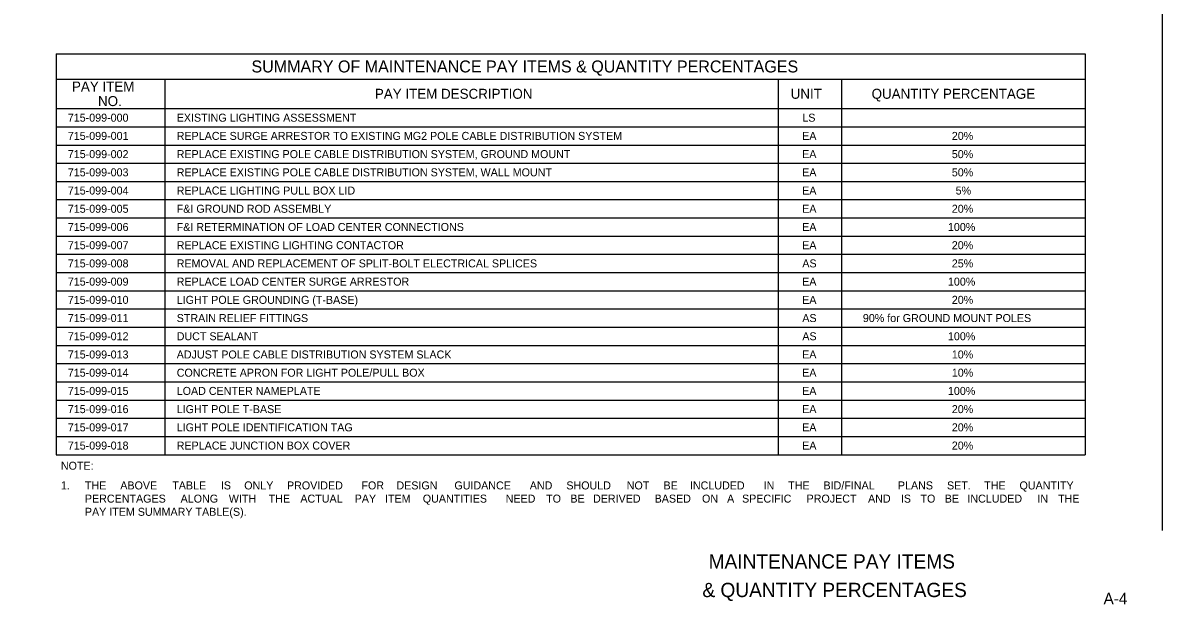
# Model space of a CAD drawing. Extents: x -55 to 2471539, y -90 to 3608906.
# Drawn here: x 543 to 1540, y -64 to 445 of the extents above; entities that cross this region are included whole.
import ezdxf

# ---------------------------------------------------------------- set-up
doc = ezdxf.new("R2010")
doc.units = 0
for name, color, linetype in [('NonPlottingEle_dp', 7, 'Continuous'), ('SumBoxBorder_dp', 7, 'Continuous'), ('SumBoxLines_dp', 7, 'Continuous'), ('SumBoxLinesMin_dp', 7, 'Continuous'), ('TextLabel', 7, 'Continuous'), ('TextMisc', 7, 'Continuous'), ('TextShtNo', 7, 'Continuous')]:
    doc.layers.add(name, color=color, linetype=linetype)

msp = doc.modelspace()

# ---------------------------------------------------------------- linework, layer by layer
at = {"layer": 'NonPlottingEle_dp'}
msp.add_lwpolyline([(0, 0), (0, 960), (1540, 960), (1540, 0)], dxfattribs=at)
at = {"layer": 'SumBoxBorder_dp'}
for p, q in [((572.5, 417.37), (1472.5, 417.37)), ((572.5, 417.37), (572.5, 66.47)), ((1472.5, 417.37), (1472.5, 66.47)), ((572.5, 369.52), (1472.5, 369.52)), ((572.5, 369.52), (1472.5, 369.52)), ((572.5, 66.47), (1472.5, 66.47))]:
    msp.add_line(p, q, dxfattribs=at)
at = {"layer": 'SumBoxLines_dp'}
for p, q in [((572.5, 395.42), (1472.5, 395.42)), ((572.5, 395.42), (1472.5, 395.42)), ((667.75, 395.42), (667.75, 66.47)), ((667.75, 395.42), (667.75, 66.47)), ((1204, 395.42), (1204, 66.47)), ((1204, 395.42), (1204, 66.47)), ((1259.5, 395.42), (1259.5, 66.47)), ((1259.5, 395.42), (1259.5, 66.47)), ((572.5, 353.57), (1472.5, 353.57)), ((580.75, 353.57), (1204, 353.57))]:
    msp.add_line(p, q, dxfattribs=at)
at = {"layer": 'SumBoxLinesMin_dp'}
for p, q in [((1204, 353.57), (1259.5, 353.57)), ((572.5, 337.62), (1259.5, 337.62)), ((572.5, 337.62), (1472.5, 337.62)), ((572.5, 321.67), (1472.5, 321.67)), ((572.5, 321.67), (1472.5, 321.67)), ((572.5, 305.72), (1472.5, 305.72)), ((572.5, 305.72), (1472.5, 305.72)), ((572.5, 289.77), (1472.5, 289.77)), ((572.5, 289.77), (1472.5, 289.77)), ((572.5, 273.82), (1472.5, 273.82)), ((572.5, 273.82), (1472.5, 273.82)), ((572.5, 257.87), (1472.5, 257.87)), ((572.5, 257.87), (1472.5, 257.87)), ((572.5, 241.92), (1472.5, 241.92)), ((572.5, 241.92), (1472.5, 241.92)), ((572.5, 225.97), (1472.5, 225.97)), ((572.5, 225.97), (1472.5, 225.97)), ((572.5, 210.02), (1472.5, 210.02)), ((572.5, 210.02), (1472.5, 210.02)), ((572.5, 194.07), (1472.5, 194.07)), ((572.5, 194.07), (1472.5, 194.07)), ((572.5, 178.12), (1472.5, 178.12)), ((572.5, 178.12), (1472.5, 178.12)), ((572.5, 162.17), (1472.5, 162.17)), ((572.5, 162.17), (1472.5, 162.17)), ((572.5, 146.22), (1472.5, 146.22)), ((572.5, 146.22), (1472.5, 146.22)), ((572.5, 130.27), (1472.5, 130.27)), ((572.5, 130.27), (1472.5, 130.27)), ((572.5, 114.32), (1472.5, 114.32)), ((580.75, 114.32), (667.75, 114.32)), ((676, 114.32), (1472.5, 114.32)), ((572.5, 98.37), (1472.5, 98.37)), ((580.75, 98.37), (667.75, 98.37)), ((1259.5, 98.37), (1472.5, 98.37)), ((572.5, 82.42), (1472.5, 82.42)), ((580.75, 82.42), (667.75, 82.42)), ((1259.5, 82.42), (1472.5, 82.42))]:
    msp.add_line(p, q, dxfattribs=at)

# ---------------------------------------------------------------- texts
at = {"layer": 'TextLabel'}
for s, height, p in [('SUMMARY OF MAINTENANCE PAY ITEMS & QUANTITY PERCENTAGES', 10.5, (743.38, 401.15)), ('PAY ITEM', 8.75, (586.39, 384.47)), ('NO.', 8.75, (609.17, 371.72)), ('PAY ITEM DESCRIPTION', 8.75, (851.34, 378.1)), ('UNIT', 8.75, (1215.03, 378.1)), ('QUANTITY PERCENTAGE', 8.75, (1285.82, 378.1)), ('715-099-000', 7, (582.75, 358.05)), ('EXISTING LIGHTING ASSESSMENT', 7, (678, 358.05)), ('LS', 7, (1225.22, 358.05)), ('715-099-001', 7, (582.75, 342.1)), ('REPLACE SURGE ARRESTOR TO EXISTING MG2 POLE CABLE DISTRIBUTION SYSTEM', 7, (678, 342.1)), ('EA', 7, (1225.07, 342.1)), ('20%', 7, (1355.97, 342.1)), ('715-099-002', 7, (582.75, 326.15)), ('REPLACE EXISTING POLE CABLE DISTRIBUTION SYSTEM, GROUND MOUNT', 7, (678, 326.15)), ('EA', 7, (1225.07, 326.15)), ('50%', 7, (1355.97, 326.15)), ('715-099-003', 7, (582.75, 310.2)), ('REPLACE EXISTING POLE CABLE DISTRIBUTION SYSTEM, WALL MOUNT', 7, (678, 310.2)), ('EA', 7, (1225.07, 310.2)), ('50%', 7, (1355.97, 310.2)), ('715-099-004', 7, (582.75, 294.25)), ('REPLACE LIGHTING PULL BOX LID', 7, (678, 294.25)), ('EA', 7, (1225.07, 294.25)), ('5%', 7, (1359.35, 294.25)), ('715-099-005', 7, (582.75, 278.3)), ('F&I GROUND ROD ASSEMBLY', 7, (678, 278.3)), ('EA', 7, (1225.07, 278.3)), ('20%', 7, (1355.97, 278.3)), ('715-099-006', 7, (582.75, 262.35)), ('F&I RETERMINATION OF LOAD CENTER CONNECTIONS', 7, (678, 262.35)), ('EA', 7, (1225.07, 262.35)), ('100%', 7, (1352.58, 262.35)), ('715-099-007', 7, (582.75, 246.4)), ('REPLACE EXISTING LIGHTING CONTACTOR', 7, (678, 246.4)), ('EA', 7, (1225.07, 246.4)), ('20%', 7, (1355.97, 246.4)), ('715-099-008', 7, (582.75, 230.45)), ('REMOVAL AND REPLACEMENT OF SPLIT-BOLT ELECTRICAL SPLICES', 7, (678, 230.45)), ('AS', 7, (1225.22, 230.45)), ('25%', 7, (1355.97, 230.45)), ('715-099-009', 7, (582.75, 214.5)), ('REPLACE LOAD CENTER SURGE ARRESTOR', 7, (678, 214.5)), ('EA', 7, (1225.07, 214.5)), ('100%', 7, (1352.58, 214.5)), ('715-099-010', 7, (582.75, 198.55)), ('LIGHT POLE GROUNDING (T-BASE)', 7, (678, 198.55)), ('EA', 7, (1225.07, 198.55)), ('20%', 7, (1355.97, 198.55)), ('715-099-011', 7, (582.75, 182.6)), ('STRAIN RELIEF FITTINGS', 7, (678, 182.6)), ('AS', 7, (1225.22, 182.6)), ('90% for GROUND MOUNT POLES', 7, (1278.16, 182.6)), ('715-099-012', 7, (582.75, 166.65)), ('DUCT SEALANT', 7, (678, 166.65)), ('AS', 7, (1225.22, 166.65)), ('100%', 7, (1352.58, 166.65)), ('715-099-013', 7, (582.75, 150.7)), ('ADJUST POLE CABLE DISTRIBUTION SYSTEM SLACK', 7, (678, 150.7)), ('EA', 7, (1225.07, 150.7)), ('10%', 7, (1355.97, 150.7)), ('715-099-014', 7, (582.75, 134.75)), ('CONCRETE APRON FOR LIGHT POLE/PULL BOX', 7, (678, 134.75)), ('EA', 7, (1225.07, 134.75)), ('10%', 7, (1355.97, 134.75)), ('715-099-015', 7, (582.75, 118.8)), ('LOAD CENTER NAMEPLATE', 7, (678, 118.8)), ('EA', 7, (1225.07, 118.8)), ('100%', 7, (1352.58, 118.8)), ('715-099-016', 7, (582.75, 102.85)), ('LIGHT POLE T-BASE', 7, (678, 102.85)), ('EA', 7, (1225.07, 102.85)), ('20%', 7, (1355.97, 102.85)), ('715-099-017', 7, (582.75, 86.9)), ('LIGHT POLE IDENTIFICATION TAG', 7, (678, 86.9)), ('EA', 7, (1225.07, 86.9)), ('20%', 7, (1355.97, 86.9)), ('715-099-018', 7, (582.75, 70.95)), ('REPLACE JUNCTION BOX COVER', 7, (678, 70.95)), ('EA', 7, (1225.07, 70.95)), ('20%', 7, (1355.97, 70.95)), ('NOTE:', 7, (576.69, 53.3)), ('1.', 7, (576.69, 36.05)), ('THE ', 7, (597.69, 36.05)), ('ABOVE ', 7, (628.64, 36.05)), ('TABLE ', 7, (674.11, 36.05)), ('IS ', 7, (716.61, 36.05)), ('ONLY ', 7, (737.05, 36.05)), ('PROVIDED ', 7, (774.45, 36.05)), ('FOR ', 7, (839.57, 36.05)), ('DESIGN ', 7, (870.18, 36.05)), ('GUIDANCE ', 7, (920.88, 36.05)), ('AND ', 7, (986.82, 36.05)), ('SHOULD ', 7, (1018.8, 36.05)), ('NOT ', 7, (1071.62, 36.05)), ('BE ', 7, (1103.8, 36.05)), ('INCLUDED ', 7, (1126.9, 36.05)), ('IN ', 7, (1191.39, 36.05)), ('THE ', 7, (1212.78, 36.05)), ('BID/FINAL ', 7, (1243.73, 36.05)), ('PLANS ', 7, (1308.82, 36.05)), ('SET. ', 7, (1351.76, 36.05)), ('THE ', 7, (1384.24, 36.05)), ('QUANTITY ', 7, (1415.19, 36.05)), ('PERCENTAGES ', 7, (597.69, 24.5)), ('ALONG ', 7, (681.43, 24.5)), ('WITH ', 7, (723.56, 24.5)), ('THE ', 7, (758.47, 24.5)), ('ACTUAL ', 7, (786.15, 24.5)), ('PAY ', 7, (833.66, 24.5)), ('ITEM ', 7, (860.21, 24.5)), ('QUANTITIES ', 7, (893.24, 24.5)), ('NEED ', 7, (965.73, 24.5)), ('TO ', 7, (1001.11, 24.5)), ('BE ', 7, (1022.31, 24.5)), ('DERIVED ', 7, (1042.13, 24.5)), ('BASED ', 7, (1096.03, 24.5)), ('ON ', 7, (1137.49, 24.5)), ('A ', 7, (1159.4, 24.5)), ('SPECIFIC ', 7, (1172.49, 24.5)), ('PROJECT ', 7, (1228.94, 24.5)), ('AND ', 7, (1282.7, 24.5)), ('IS ', 7, (1311.41, 24.5)), ('TO ', 7, (1328.57, 24.5)), ('BE ', 7, (1349.78, 24.5)), ('INCLUDED ', 7, (1369.6, 24.5)), ('IN ', 7, (1430.81, 24.5)), ('THE ', 7, (1448.92, 24.5)), ('PAY ITEM SUMMARY TABLE(S).', 7, (597.69, 12.95))]:
    msp.add_text(s, height=height, dxfattribs=at).set_placement(p)
at = {"layer": 'TextMisc'}
for s, p in [('MAINTENANCE PAY ITEMS', (1143.25, -33.24)), ('& QUANTITY PERCENTAGES', (1137.8, -58.24))]:
    msp.add_text(s, height=12.5, dxfattribs=at).set_placement(p)
at = {"layer": 'TextShtNo'}
msp.add_text(' A-4 ', height=10, dxfattribs=at).set_placement((1484.99, -64.49))

doc.saveas('drawing.dxf')
